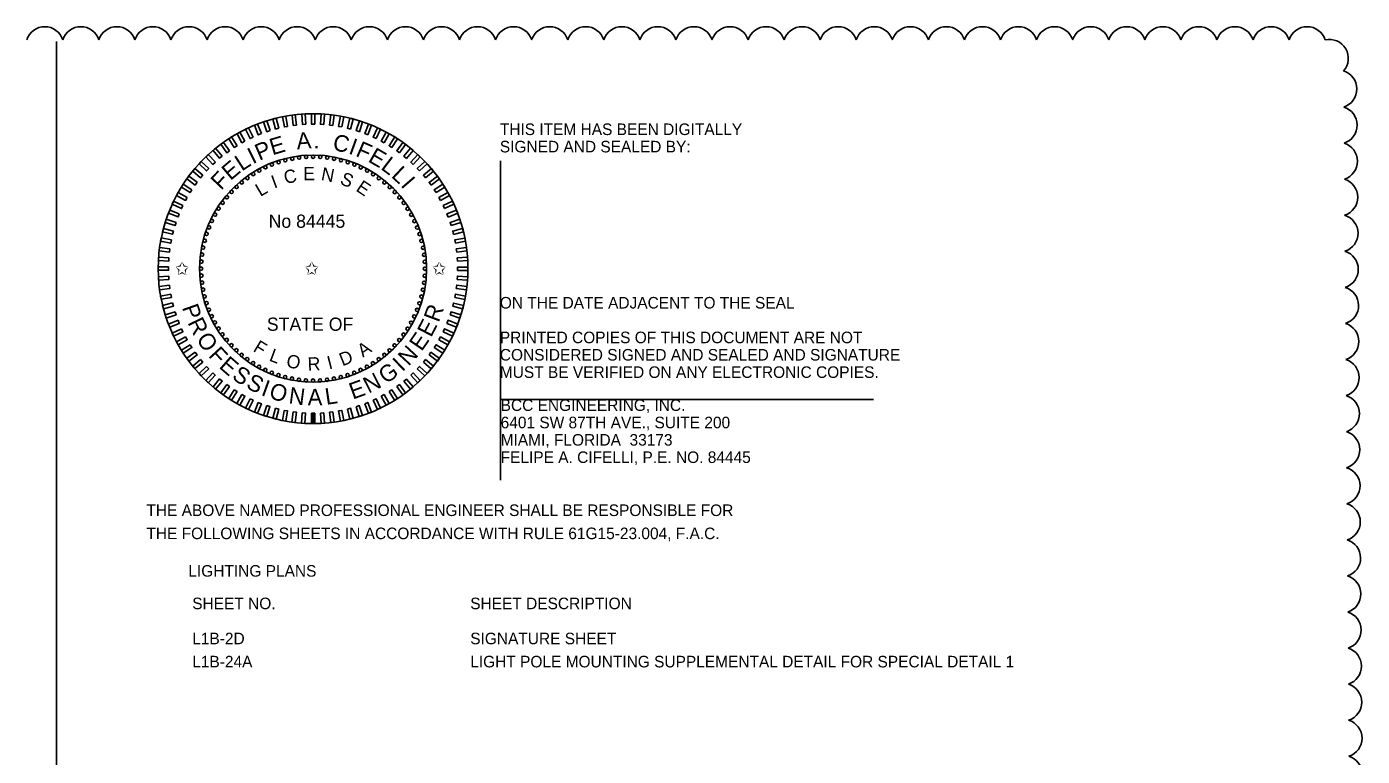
# Model space of a CAD drawing. Extents: x -811.2 to -795, y -2307.6 to -2235.1.
# Drawn here: x -803.27 to -795.18, y -2289.23 to -2284.82 of the extents above; entities that cross this region are included whole.
import ezdxf

# ---------------------------------------------------------------- set-up
doc = ezdxf.new("R2010")
doc.units = 0
for name, color, linetype in [('AdhocPoint_dp', 7, 'Continuous'), ('Cloud_dp', 7, 'Continuous'), ('Logo_dp', 7, 'Continuous'), ('TeleMisc', 7, 'Continuous'), ('TextDetails', 7, 'Continuous'), ('TextMisc', 7, 'Continuous'), ('TextNotes', 7, 'Continuous')]:
    doc.layers.add(name, color=color, linetype=linetype)

msp = doc.modelspace()

# ---------------------------------------------------------------- linework, layer by layer
at = {"layer": 'AdhocPoint_dp'}
for p, q in [((-800.3974, -2285.6292), (-800.3974, -2287.5639)), ((-800.3974, -2287.0739), (-798.1407, -2287.0739))]:
    msp.add_line(p, q, dxfattribs=at)
at = {"layer": 'Cloud_dp'}
for centre, start, end in [((-803.1571, -2284.9327), 17.50004, 162.50004), ((-802.9388, -2284.9327), 17.5, 162.5), ((-802.7205, -2284.9327), 17.5, 162.5), ((-802.5022, -2284.9327), 17.5, 162.5), ((-802.2839, -2284.9327), 17.5, 162.5), ((-802.0655, -2284.9327), 17.5, 162.5), ((-801.8472, -2284.9327), 17.5, 162.5), ((-801.6289, -2284.9327), 17.5, 162.5), ((-801.4106, -2284.9327), 17.5, 162.5), ((-801.1922, -2284.9327), 17.5, 162.5), ((-800.9739, -2284.9327), 17.5, 162.5), ((-800.7556, -2284.9327), 17.5, 162.5), ((-800.5373, -2284.9327), 17.5, 162.5), ((-800.3189, -2284.9327), 17.5, 162.5), ((-800.1006, -2284.9327), 17.5, 162.5), ((-799.8823, -2284.9327), 17.5, 162.5), ((-799.664, -2284.9327), 17.5, 162.5), ((-799.4456, -2284.9327), 17.5, 162.5), ((-799.2273, -2284.9327), 17.5, 162.5), ((-799.009, -2284.9327), 17.5, 162.5), ((-798.7907, -2284.9327), 17.5, 162.5), ((-798.5724, -2284.9327), 17.5, 162.5), ((-798.354, -2284.9327), 17.5, 162.5), ((-798.1357, -2284.9327), 17.5, 162.5), ((-797.9174, -2284.9327), 17.5, 162.5), ((-797.6991, -2284.9327), 17.5, 162.5), ((-797.4807, -2284.9327), 17.5, 162.5), ((-797.2624, -2284.9327), 17.5, 162.5), ((-797.0441, -2284.9327), 17.5, 162.5), ((-796.8258, -2284.9327), 17.5, 162.5), ((-796.6074, -2284.9327), 17.5, 162.5), ((-796.3891, -2284.9327), 17.5, 162.5), ((-796.1708, -2284.9327), 17.5, 162.5), ((-795.9525, -2284.9327), 17.5, 162.5), ((-795.7341, -2284.9327), 17.5, 162.5), ((-795.5158, -2284.9327), 17.5, 162.5), ((-795.3807, -2285.0098), 318.11161, 103.11161), ((-795.329, -2285.1956), 287.95289, 72.95289), ((-795.3273, -2285.414), 287.95289, 72.95289), ((-795.3256, -2285.6323), 287.95289, 72.95289), ((-795.3239, -2285.8506), 287.95289, 72.95289), ((-795.3221, -2286.0689), 287.95289, 72.95289), ((-795.3204, -2286.2872), 287.95289, 72.95289), ((-795.3187, -2286.5055), 287.95289, 72.95289), ((-795.317, -2286.7239), 287.95289, 72.95289), ((-795.3152, -2286.9422), 287.95289, 72.95289), ((-795.3135, -2287.1605), 287.95289, 72.95289), ((-795.3118, -2287.3788), 287.95289, 72.95289), ((-795.3101, -2287.5971), 287.95289, 72.95289), ((-795.3083, -2287.8154), 287.95289, 72.95289), ((-795.3066, -2288.0338), 287.95289, 72.95289), ((-795.3049, -2288.2521), 287.95289, 72.95289), ((-795.3032, -2288.4704), 287.95289, 72.95289), ((-795.3014, -2288.6887), 287.95289, 72.95289), ((-795.2997, -2288.907), 287.95289, 72.95289), ((-795.298, -2289.1253), 287.95289, 72.95289), ((-795.2963, -2289.3437), 287.95289, 72.95289)]:
    msp.add_arc(centre, 0.1145, start, end, dxfattribs=at)
at = {"layer": 'TextDetails'}
for radius in [0.9375, 0.6875]:
    msp.add_circle((-801.5329, -2286.2827), radius, dxfattribs=at)
at = {"layer": 'TextMisc'}
for p, q in [((-801.5429, -2287.2202), (-801.5431, -2287.1577)), ((-801.5329, -2287.2202), (-801.5331, -2287.1577)), ((-801.5229, -2287.2202), (-801.5231, -2287.1577))]:
    msp.add_line(p, q, dxfattribs=at)
for points in [[(-801.8456, -2285.4654), (-801.8643, -2285.4728), (-801.8873, -2285.4148), (-801.8686, -2285.4073)], [(-801.7936, -2285.4474), (-801.8128, -2285.4536), (-801.8321, -2285.3942), (-801.8129, -2285.388)], [(-801.7407, -2285.4326), (-801.7602, -2285.4377), (-801.7757, -2285.3772), (-801.7562, -2285.3722)], [(-801.6869, -2285.4213), (-801.7067, -2285.4251), (-801.7184, -2285.3637), (-801.6986, -2285.3599)], [(-801.6325, -2285.4133), (-801.6525, -2285.4158), (-801.6603, -2285.3539), (-801.6403, -2285.3514)], [(-801.5777, -2285.4088), (-801.5978, -2285.41), (-801.6018, -2285.3477), (-801.5816, -2285.3465)], [(-801.5227, -2285.4077), (-801.5429, -2285.4077), (-801.5429, -2285.3452), (-801.5227, -2285.3452)], [(-801.4678, -2285.41), (-801.488, -2285.4088), (-801.484, -2285.3465), (-801.4639, -2285.3477)], [(-801.4131, -2285.4159), (-801.4332, -2285.4133), (-801.4253, -2285.3514), (-801.4053, -2285.3539)], [(-801.359, -2285.4251), (-801.3788, -2285.4213), (-801.3671, -2285.36), (-801.3473, -2285.3638)], [(-801.3054, -2285.4377), (-801.325, -2285.4327), (-801.3095, -2285.3722), (-801.2899, -2285.3772)], [(-801.2528, -2285.4537), (-801.272, -2285.4474), (-801.2527, -2285.388), (-801.2335, -2285.3943)], [(-801.2013, -2285.4729), (-801.2201, -2285.4654), (-801.1971, -2285.4074), (-801.1783, -2285.4148)], [(-801.9932, -2285.5384), (-802.0102, -2285.5493), (-802.0437, -2285.4965), (-802.0266, -2285.4857)], [(-801.9455, -2285.511), (-801.9632, -2285.5207), (-801.9933, -2285.466), (-801.9756, -2285.4563)], [(-801.8963, -2285.4866), (-801.9145, -2285.4952), (-801.9411, -2285.4387), (-801.9229, -2285.4301)], [(-801.1511, -2285.4953), (-801.1694, -2285.4867), (-801.1428, -2285.4302), (-801.1246, -2285.4388)], [(-801.1024, -2285.5208), (-801.1201, -2285.5111), (-801.0901, -2285.4564), (-801.0724, -2285.4661)], [(-801.0555, -2285.5494), (-801.0725, -2285.5385), (-801.039, -2285.4858), (-801.022, -2285.4966)], [(-802.0828, -2285.602), (-802.0984, -2285.6149), (-802.1382, -2285.5668), (-802.1226, -2285.5539)], [(-802.039, -2285.5688), (-802.0553, -2285.5807), (-802.092, -2285.5302), (-802.0757, -2285.5183)], [(-801.0104, -2285.5808), (-801.0267, -2285.5689), (-800.99, -2285.5184), (-800.9737, -2285.5303)], [(-800.9673, -2285.615), (-800.9829, -2285.6021), (-800.9431, -2285.554), (-800.9275, -2285.5669)], [(-802.1638, -2285.6763), (-802.1776, -2285.691), (-802.2232, -2285.6483), (-802.2093, -2285.6335)], [(-802.1245, -2285.6379), (-802.1392, -2285.6517), (-802.182, -2285.6062), (-802.1672, -2285.5924)], [(-800.9265, -2285.6518), (-800.9412, -2285.638), (-800.8985, -2285.5925), (-800.8838, -2285.6063)], [(-800.8881, -2285.6911), (-800.9019, -2285.6764), (-800.8564, -2285.6337), (-800.8426, -2285.6484)], [(-802.2348, -2285.7601), (-802.2467, -2285.7765), (-802.2972, -2285.7398), (-802.2854, -2285.7234)], [(-802.2007, -2285.7171), (-802.2135, -2285.7327), (-802.2616, -2285.6929), (-802.2488, -2285.6773)], [(-800.8522, -2285.7328), (-800.8651, -2285.7172), (-800.817, -2285.6774), (-800.8041, -2285.693)], [(-800.819, -2285.7766), (-800.8309, -2285.7603), (-800.7804, -2285.7236), (-800.7685, -2285.7399)], [(-802.2663, -2285.8052), (-802.2771, -2285.8223), (-802.3298, -2285.7888), (-802.319, -2285.7718)], [(-800.7887, -2285.8224), (-800.7995, -2285.8054), (-800.7467, -2285.7719), (-800.7359, -2285.789)], [(-802.3203, -2285.9009), (-802.3289, -2285.9192), (-802.3854, -2285.8926), (-802.3768, -2285.8743)], [(-802.2948, -2285.8522), (-802.3045, -2285.8699), (-802.3593, -2285.8398), (-802.3495, -2285.8222)], [(-800.7612, -2285.8701), (-800.7709, -2285.8524), (-800.7162, -2285.8223), (-800.7065, -2285.84)], [(-800.7368, -2285.9194), (-800.7454, -2285.9011), (-800.6889, -2285.8745), (-800.6803, -2285.8928)], [(-802.3428, -2285.9511), (-802.3502, -2285.9699), (-802.4082, -2285.9469), (-802.4008, -2285.9281)], [(-800.7156, -2285.9701), (-800.723, -2285.9513), (-800.665, -2285.9283), (-800.6575, -2285.9471)], [(-802.3779, -2286.0552), (-802.3829, -2286.0748), (-802.4434, -2286.0593), (-802.4384, -2286.0397)], [(-802.362, -2286.0026), (-802.3682, -2286.0218), (-802.4276, -2286.0025), (-802.4214, -2285.9833)], [(-800.6976, -2286.022), (-800.7038, -2286.0028), (-800.6444, -2285.9835), (-800.6382, -2286.0027)], [(-800.6828, -2286.075), (-800.6879, -2286.0554), (-800.6274, -2286.0399), (-800.6224, -2286.0594)], [(-802.3905, -2286.1087), (-802.3943, -2286.1286), (-802.4557, -2286.1169), (-802.4519, -2286.097)], [(-800.6715, -2286.1288), (-800.6753, -2286.1089), (-800.6139, -2286.0972), (-800.6101, -2286.1171)], [(-802.4056, -2286.2176), (-802.4069, -2286.2377), (-802.4692, -2286.2338), (-802.4679, -2286.2137)], [(-802.3998, -2286.1629), (-802.4023, -2286.183), (-802.4643, -2286.1751), (-802.4617, -2286.1551)], [(-800.6635, -2286.1831), (-800.666, -2286.1631), (-800.6041, -2286.1553), (-800.6016, -2286.1753)], [(-800.659, -2286.2379), (-800.6602, -2286.2178), (-800.5979, -2286.2139), (-800.5967, -2286.234)], [(-802.408, -2286.2725), (-802.408, -2286.2927), (-802.4704, -2286.2927), (-802.4704, -2286.2725)], [(-800.6579, -2286.2929), (-800.6579, -2286.2727), (-800.5955, -2286.2727), (-800.5955, -2286.2929)], [(-802.4069, -2286.3275), (-802.4056, -2286.3476), (-802.4679, -2286.3516), (-802.4692, -2286.3314)], [(-800.6603, -2286.3478), (-800.659, -2286.3277), (-800.5967, -2286.3316), (-800.5979, -2286.3517)], [(-802.4023, -2286.3823), (-802.3998, -2286.4023), (-802.4617, -2286.4101), (-802.4643, -2286.3901)], [(-802.3944, -2286.4367), (-802.3906, -2286.4565), (-802.4519, -2286.4682), (-802.4557, -2286.4484)], [(-800.6753, -2286.4567), (-800.6715, -2286.4369), (-800.6102, -2286.4486), (-800.614, -2286.4684)], [(-800.6661, -2286.4025), (-800.6635, -2286.3825), (-800.6016, -2286.3903), (-800.6041, -2286.4103)], [(-802.383, -2286.4905), (-802.378, -2286.51), (-802.4385, -2286.5255), (-802.4435, -2286.506)], [(-800.6879, -2286.5102), (-800.6829, -2286.4906), (-800.6224, -2286.5062), (-800.6274, -2286.5257)], [(-802.3683, -2286.5434), (-802.362, -2286.5626), (-802.4214, -2286.5819), (-802.4277, -2286.5627)], [(-802.3503, -2286.5954), (-802.3428, -2286.6141), (-802.4009, -2286.6371), (-802.4083, -2286.6183)], [(-800.7231, -2286.6143), (-800.7157, -2286.5955), (-800.6576, -2286.6185), (-800.665, -2286.6373)], [(-800.7039, -2286.5628), (-800.6976, -2286.5436), (-800.6382, -2286.5629), (-800.6445, -2286.5821)], [(-802.329, -2286.6461), (-802.3204, -2286.6643), (-802.3769, -2286.6909), (-802.3855, -2286.6726)], [(-802.3046, -2286.6953), (-802.2949, -2286.713), (-802.3496, -2286.7431), (-802.3593, -2286.7254)], [(-800.771, -2286.7132), (-800.7613, -2286.6955), (-800.7066, -2286.7256), (-800.7163, -2286.7433)], [(-800.7455, -2286.6645), (-800.7369, -2286.6462), (-800.6804, -2286.6728), (-800.689, -2286.6911)], [(-802.2772, -2286.743), (-802.2664, -2286.76), (-802.3191, -2286.7935), (-802.3299, -2286.7764)], [(-800.7996, -2286.7602), (-800.7888, -2286.7431), (-800.736, -2286.7766), (-800.7468, -2286.7936)], [(-802.2468, -2286.7888), (-802.235, -2286.8051), (-802.2855, -2286.8418), (-802.2973, -2286.8255)], [(-802.2136, -2286.8326), (-802.2008, -2286.8482), (-802.2489, -2286.888), (-802.2617, -2286.8724)], [(-800.8652, -2286.8483), (-800.8523, -2286.8328), (-800.8042, -2286.8726), (-800.8171, -2286.8881)], [(-800.831, -2286.8053), (-800.8191, -2286.789), (-800.7686, -2286.8257), (-800.7805, -2286.842)], [(-802.1778, -2286.8743), (-802.1639, -2286.889), (-802.2095, -2286.9317), (-802.2233, -2286.917)], [(-802.1393, -2286.9136), (-802.1246, -2286.9274), (-802.1674, -2286.9729), (-802.1821, -2286.9591)], [(-800.9413, -2286.9276), (-800.9266, -2286.9137), (-800.8839, -2286.9593), (-800.8986, -2286.9731)], [(-800.902, -2286.8891), (-800.8882, -2286.8744), (-800.8427, -2286.9172), (-800.8565, -2286.9319)], [(-802.0985, -2286.9504), (-802.083, -2286.9633), (-802.1228, -2287.0114), (-802.1383, -2286.9986)], [(-802.0555, -2286.9846), (-802.0392, -2286.9965), (-802.0759, -2287.047), (-802.0922, -2287.0352)], [(-802.0104, -2287.0161), (-801.9933, -2287.0269), (-802.0268, -2287.0796), (-802.0438, -2287.0688)], [(-801.0727, -2287.027), (-801.0556, -2287.0162), (-801.0222, -2287.0689), (-801.0392, -2287.0797)], [(-801.0268, -2286.9966), (-801.0105, -2286.9847), (-800.9738, -2287.0353), (-800.9901, -2287.0471)], [(-800.983, -2286.9634), (-800.9675, -2286.9506), (-800.9277, -2286.9987), (-800.9432, -2287.0115)], [(-801.9634, -2287.0446), (-801.9457, -2287.0543), (-801.9758, -2287.109), (-801.9935, -2287.0993)], [(-801.9147, -2287.0701), (-801.8964, -2287.0787), (-801.923, -2287.1352), (-801.9413, -2287.1266)], [(-801.8645, -2287.0925), (-801.8457, -2287.1), (-801.8687, -2287.158), (-801.8875, -2287.1506)], [(-801.2203, -2287.1), (-801.2015, -2287.0926), (-801.1785, -2287.1507), (-801.1973, -2287.1581)], [(-801.1696, -2287.0788), (-801.1513, -2287.0702), (-801.1247, -2287.1267), (-801.143, -2287.1353)], [(-801.1203, -2287.0544), (-801.1026, -2287.0447), (-801.0725, -2287.0994), (-801.0902, -2287.1091)], [(-801.813, -2287.1118), (-801.7938, -2287.118), (-801.8131, -2287.1774), (-801.8323, -2287.1712)], [(-801.7604, -2287.1277), (-801.7408, -2287.1327), (-801.7564, -2287.1932), (-801.7759, -2287.1882)], [(-801.7069, -2287.1403), (-801.6871, -2287.1441), (-801.6988, -2287.2055), (-801.7186, -2287.2017)], [(-801.6527, -2287.1496), (-801.6327, -2287.1521), (-801.6405, -2287.214), (-801.6605, -2287.2115)], [(-801.598, -2287.1554), (-801.5779, -2287.1566), (-801.5818, -2287.219), (-801.602, -2287.2177)], [(-801.5431, -2287.1577), (-801.5229, -2287.1577), (-801.5229, -2287.2202), (-801.5431, -2287.2202)], [(-801.4881, -2287.1567), (-801.468, -2287.1554), (-801.4641, -2287.2177), (-801.4842, -2287.219)], [(-801.4334, -2287.1521), (-801.4133, -2287.1496), (-801.4055, -2287.2115), (-801.4255, -2287.2141)], [(-801.379, -2287.1442), (-801.3591, -2287.1404), (-801.3474, -2287.2017), (-801.3673, -2287.2055)], [(-801.3252, -2287.1328), (-801.3056, -2287.1278), (-801.2901, -2287.1882), (-801.3096, -2287.1933)], [(-801.2722, -2287.1181), (-801.253, -2287.1118), (-801.2337, -2287.1712), (-801.2529, -2287.1774)]]:
    msp.add_lwpolyline(points, close=True, dxfattribs=at)
for centre in [(-801.7818, -2285.6526), (-801.7417, -2285.6382), (-801.7009, -2285.6264), (-801.6593, -2285.6171), (-801.6173, -2285.6105), (-801.5749, -2285.6065), (-801.5324, -2285.6052), (-801.4898, -2285.6066), (-801.4475, -2285.6107), (-801.4054, -2285.6173), (-801.3639, -2285.6267), (-801.323, -2285.6386), (-801.283, -2285.653), (-801.9307, -2285.7343), (-801.8955, -2285.7104), (-801.8588, -2285.6888), (-801.8209, -2285.6695), (-801.244, -2285.67), (-801.2061, -2285.6893), (-801.1694, -2285.711), (-801.1343, -2285.735), (-802.0264, -2285.8185), (-801.9963, -2285.7885), (-801.9643, -2285.7604), (-801.1007, -2285.7611), (-801.0688, -2285.7892), (-801.0387, -2285.8194), (-802.0807, -2285.884), (-802.0546, -2285.8504), (-801.0106, -2285.8513), (-800.9845, -2285.885), (-802.1263, -2285.9558), (-802.1046, -2285.9192), (-800.9606, -2285.9202), (-800.939, -2285.9568), (-802.1626, -2286.0328), (-802.1457, -2285.9937), (-800.9197, -2285.9948), (-800.9028, -2286.0338), (-802.189, -2286.1137), (-802.1771, -2286.0728), (-800.8884, -2286.0739), (-800.8766, -2286.1148), (-802.205, -2286.1972), (-802.1983, -2286.1552), (-800.8673, -2286.1563), (-800.8607, -2286.1984), (-802.2104, -2286.2821), (-802.209, -2286.2396), (-800.8568, -2286.2407), (-800.8555, -2286.2833), (-802.2091, -2286.3247), (-802.2051, -2286.3671), (-800.8609, -2286.3682), (-800.8568, -2286.3258), (-802.1985, -2286.4091), (-802.1892, -2286.4506), (-800.8769, -2286.4517), (-800.8676, -2286.4102), (-802.1774, -2286.4915), (-802.163, -2286.5316), (-800.9032, -2286.5326), (-800.8888, -2286.4926), (-802.1462, -2286.5707), (-802.1269, -2286.6086), (-800.9395, -2286.6096), (-800.9202, -2286.5717), (-802.1052, -2286.6452), (-802.0813, -2286.6805), (-802.0553, -2286.7141), (-800.9852, -2286.6814), (-800.9612, -2286.6462), (-802.0272, -2286.7461), (-801.9971, -2286.7762), (-801.0696, -2286.777), (-801.0395, -2286.7469), (-801.0113, -2286.715), (-801.9652, -2286.8044), (-801.9316, -2286.8305), (-801.8964, -2286.8544), (-801.1704, -2286.855), (-801.1352, -2286.8311), (-801.1015, -2286.8051), (-801.8598, -2286.8761), (-801.8219, -2286.8955), (-801.7828, -2286.9124), (-801.7428, -2286.9268), (-801.7019, -2286.9388), (-801.6604, -2286.9481), (-801.6184, -2286.9548), (-801.4486, -2286.9549), (-801.4065, -2286.9483), (-801.365, -2286.939), (-801.3241, -2286.9272), (-801.2841, -2286.9128), (-801.245, -2286.8959), (-801.207, -2286.8767), (-801.576, -2286.9588), (-801.5329, -2286.9602), (-801.4909, -2286.9589)]:
    msp.add_circle(centre, 0.01, dxfattribs=at)
at = {"layer": 'TextNotes'}
msp.add_line((-803.0858, -2294.5069), (-803.0858, -2284.9069), dxfattribs=at)

# ---------------------------------------------------------------- texts
at = {"layer": 'Logo_dp'}
for s, p in [('THIS ITEM HAS BEEN DIGITALLY', (-800.4024, -2285.474)), ('SIGNED AND SEALED BY:', (-800.4024, -2285.579)), ('ON THE DATE ADJACENT TO THE SEAL', (-800.4024, -2286.524)), ('PRINTED COPIES OF THIS DOCUMENT ARE NOT ', (-800.4024, -2286.734)), ('CONSIDERED SIGNED AND SEALED AND SIGNATURE ', (-800.4024, -2286.839)), ('MUST BE VERIFIED ON ANY ELECTRONIC COPIES.', (-800.4024, -2286.944)), ('BCC ENGINEERING, INC.', (-800.3974, -2287.1439)), ('6401 SW 87TH AVE., SUITE 200', (-800.3974, -2287.2489)), ('MIAMI, FLORIDA  33173', (-800.3974, -2287.3539)), ('FELIPE A. CIFELLI, P.E. NO. 84445', (-800.3974, -2287.4589)), ('THE ABOVE NAMED PROFESSIONAL ENGINEER SHALL BE RESPONSIBLE FOR ', (-802.5415, -2287.78)), ('THE FOLLOWING SHEETS IN ACCORDANCE WITH RULE 61G15-23.004, F.A.C.', (-802.5415, -2287.92)), ('LIGHTING PLANS', (-802.2878, -2288.147))]:
    msp.add_text(s, height=0.07, dxfattribs=at).set_placement(p)
at = {"layer": 'TeleMisc'}
for s, p in [('SHEET NO.', (-802.2643, -2288.344)), ('SHEET DESCRIPTION', (-800.5815, -2288.344)), ('L1B-2D', (-802.2643, -2288.5562)), ('SIGNATURE SHEET', (-800.5815, -2288.5562)), ('L1B-24A', (-802.2643, -2288.6962)), ('LIGHT POLE MOUNTING SUPPLEMENTAL DETAIL FOR SPECIAL DETAIL 1', (-800.5815, -2288.6962))]:
    msp.add_text(s, height=0.07, dxfattribs=at).set_placement(p)
at = {"layer": 'TextMisc'}
for s, height, rotation, p in [('E', 0.1, 16.54261, (-801.7793, -2285.597)), ('A', 0.1, 4.42103, (-801.6298, -2285.5605)), ('C', 0.1, 347.7999, (-801.4192, -2285.563)), ('I', 0.1, 26.81606, (-801.8977, -2285.6519)), ('P', 0.1, 23.28287, (-801.8581, -2285.6306)), ('.', 0.1, 356.65403, (-801.5313, -2285.5541)), ('I', 0.1, 340.0631, (-801.3234, -2285.5848)), ('F', 0.1, 336.52991, (-801.2807, -2285.5991)), ('E', 0.1, 330.07956, (-801.2055, -2285.6317)), ('E', 0.1, 40.12142, (-802.033, -2285.7528)), ('L', 0.1, 33.07918, (-801.9643, -2285.6955)), ('L', 0.1, 323.03732, (-801.1282, -2285.6768)), ('F', 0.1, 46.57177, (-802.0894, -2285.8123)), ('I', 0.08, 20.01168, (-801.7686, -2285.7986)), ('C', 0.08, 12.20255, (-801.7007, -2285.7711)), ('E', 0.08, 0.41861, (-801.5926, -2285.7476)), ('N', 0.08, 349.29143, (-801.4883, -2285.7462)), ('S', 0.08, 337.02207, (-801.3753, -2285.7679)), ('L', 0.1, 316.7742, (-801.0645, -2285.7246)), ('I', 0.1, 310.51108, (-801.0064, -2285.779)), ('L', 0.08, 30.40215, (-801.8521, -2285.8491)), ('E', 0.08, 325.86633, (-801.2786, -2285.8081)), ('P', 0.1, 289.40551, (-802.3276, -2286.5173)), ('R', 0.1, 69.5134, (-800.7727, -2286.6124)), ('R', 0.1, 296.14576, (-802.2946, -2286.6089)), ('E', 0.1, 62.47116, (-800.8189, -2286.7031)), ('O', 0.1, 303.96711, (-802.2431, -2286.7096)), ('E', 0.1, 55.42892, (-800.8758, -2286.7875)), ('F', 0.1, 312.62798, (-802.1707, -2286.8116)), ('F', 0.08, 328.72408, (-801.901, -2286.7793)), ('L', 0.08, 339.29159, (-801.8037, -2286.8384)), ('D', 0.08, 22.01279, (-801.3548, -2286.8746)), ('A', 0.08, 34.49917, (-801.2311, -2286.8221)), ('N', 0.1, 47.17876, (-800.9551, -2286.8766)), ('E', 0.1, 319.07833, (-802.1073, -2286.8799)), ('O', 0.08, 349.68206, (-801.699, -2286.8781)), ('R', 0.08, 2.33977, (-801.5645, -2286.9)), ('I', 0.08, 14.20366, (-801.4369, -2286.8933)), ('G', 0.1, 35.11153, (-801.092, -2286.9842)), ('I', 0.1, 43.64556, (-800.9928, -2286.911)), ('S', 0.1, 326.12056, (-802.0297, -2286.9459)), ('S', 0.1, 333.193, (-801.9443, -2287.002)), ('N', 0.1, 26.86136, (-801.1972, -2287.0403)), ('I', 0.1, 340.26543, (-801.8526, -2287.0472)), ('O', 0.1, 343.79863, (-801.8049, -2287.0654)), ('N', 0.1, 352.45949, (-801.6839, -2287.0974)), ('A', 0.1, 0.70966, (-801.5655, -2287.1107)), ('L', 0.1, 8.47665, (-801.4533, -2287.1075)), ('E', 0.1, 19.81912, (-801.2926, -2287.0757))]:
    msp.add_text(s, height=height, rotation=rotation, dxfattribs=at).set_placement(p)
for s, p in [('No 84445', (-801.8019, -2286.0355)), ('✩', (-802.3679, -2286.3207)), ('✩', (-801.5832, -2286.3207)), ('✩', (-800.8113, -2286.3207)), ('STATE OF', (-801.8126, -2286.6589))]:
    msp.add_text(s, height=0.08, dxfattribs=at).set_placement(p)

doc.saveas('drawing.dxf')
